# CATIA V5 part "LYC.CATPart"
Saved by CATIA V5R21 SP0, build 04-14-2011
Part number: LYC.SLDPRT
Bounding box of the stored display mesh (mm): x -1.7 to 1.7, y -1.65 to 1.65, z -1.105 to 0.8
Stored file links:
  C:\Users\user\Desktop\CATIA文件\0-最新文件\LYC\LYC.CATPart
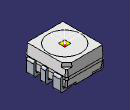
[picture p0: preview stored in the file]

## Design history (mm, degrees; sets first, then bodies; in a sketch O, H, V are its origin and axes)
AxisSystem1: origin (-0.0017, 0.0021, 0.8), X (-1, 0, 0), Y (0, -1, 0), Z (0, 0, 1)
Set1
  DatumSurface1 to DatumSurface139
  Circle1: stored without definition
  Circle2: stored without definition
  DatumCurve1 to DatumCurve5
  Line1 to Line5: stored without definition
  DatumCurve6 to DatumCurve12
  Line6: stored without definition
  Circle3 to Circle8: stored without definition
  Line7: stored without definition
  Circle9: stored without definition
  Line8: stored without definition
  Circle10: stored without definition
  Line9: stored without definition
  Circle11: stored without definition
  Line10: stored without definition
  Circle12: stored without definition
  Line11 to Line13: stored without definition
  Circle13: stored without definition
  Line14: stored without definition
  Circle14: stored without definition
  Line15 to Line23: stored without definition
  Circle15: stored without definition
  Line24: stored without definition
  Circle16: stored without definition
  Line25 to Line27: stored without definition
  Circle17: stored without definition
  Line28: stored without definition
  Circle18: stored without definition
  Line29 to Line40: stored without definition
  Circle19: stored without definition
  Line41: stored without definition
  Circle20: stored without definition
  Line42 to Line44: stored without definition
  Circle21: stored without definition
  Line45: stored without definition
  Circle22: stored without definition
  Line46 to Line54: stored without definition
  Circle23: stored without definition
  Line55: stored without definition
  Circle24: stored without definition
  Line56 to Line58: stored without definition
  Circle25: stored without definition
  Line59: stored without definition
  Circle26: stored without definition
  Line60 to Line65: stored without definition
  Circle27 to Circle29: stored without definition
  Line66: stored without definition
  Circle30: stored without definition
  Line67: stored without definition
  Circle31: stored without definition
  Line68: stored without definition
  Circle32: stored without definition
  Line69: stored without definition
  Circle33 to Circle38: stored without definition
  Line70: stored without definition
  Line71: stored without definition
  Circle39: stored without definition
  Circle40: stored without definition
  Line72 to Line78: stored without definition
  DatumCurve13
  DatumCurve14
  Line79: stored without definition
  Line80: stored without definition
  Circle41: stored without definition
  Line81: stored without definition
  DatumCurve15
  Line82: stored without definition
  Line83: stored without definition
  DatumCurve16
  Line84: stored without definition
  Circle42: stored without definition
  Line85: stored without definition
  DatumCurve17
  Line86: stored without definition
  DatumCurve18
  Line87 to Line89: stored without definition
  DatumCurve19
  DatumCurve20
  Line90: stored without definition
  Circle43: stored without definition
  Line91: stored without definition
  Circle44: stored without definition
  Circle45: stored without definition
  Line92: stored without definition
  Circle46 to Circle49: stored without definition
  Line93: stored without definition
  Circle50: stored without definition
  Line94 to Line99: stored without definition
  DatumCurve21
  Line100: stored without definition
  Circle51: stored without definition
  Line101: stored without definition
  Line102: stored without definition
  DatumCurve22
  Line103 to Line111: stored without definition
  DatumCurve23
  Line112: stored without definition
  DatumCurve24
  Line113: stored without definition
  Circle52: stored without definition
  DatumCurve25
  Line114 to Line116: stored without definition
  Circle53: stored without definition
  Line117 to Line124: stored without definition
  DatumCurve26
  Line125: stored without definition
  DatumCurve27 to DatumCurve29
  Circle54: stored without definition
  Line126: stored without definition
  Circle55: stored without definition
  Line127 to Line129: stored without definition
  DatumCurve30
  Line130: stored without definition
  Line131: stored without definition
  DatumCurve31
  Line132 to Line139: stored without definition
  DatumCurve32
  Line140 to Line143: stored without definition
  DatumCurve33
  Line144 to Line169: stored without definition
  Circle56: stored without definition
  Line170: stored without definition
  Circle57: stored without definition
  Line171 to Line173: stored without definition
  Circle58: stored without definition
  Line174: stored without definition
  Circle59: stored without definition
  Line175 to Line183: stored without definition
  Circle60: stored without definition
  Line184: stored without definition
  Circle61: stored without definition
  Line185 to Line187: stored without definition
  Circle62: stored without definition
  Circle63: stored without definition
  Line188: stored without definition
  Circle64: stored without definition
  Circle65: stored without definition
  Line189 to Line191: stored without definition
  Circle66: stored without definition
  Line192: stored without definition
  Circle67: stored without definition
  Line193 to Line201: stored without definition
  Circle68: stored without definition
  Line202: stored without definition
  Circle69: stored without definition
  Line203 to Line205: stored without definition
  Circle70: stored without definition
  Line206: stored without definition
  Circle71: stored without definition
  Line207: stored without definition
  Line208: stored without definition
  Circle72: stored without definition
  Line209: stored without definition
  Circle73: stored without definition
  Line210 to Line212: stored without definition
  Circle74: stored without definition
  Line213: stored without definition
  Circle75: stored without definition
  Line214 to Line216: stored without definition
  Circle76: stored without definition
  Line217 to Line219: stored without definition
  Circle77: stored without definition
  Line220 to Line227: stored without definition
  Circle78: stored without definition
  Line228: stored without definition
  Line229: stored without definition
  Circle79: stored without definition
  Line230: stored without definition
  Circle80: stored without definition
  Line231: stored without definition
  Circle81: stored without definition
  Line232 to Line234: stored without definition
  Circle82: stored without definition
  Line235: stored without definition
  Circle83: stored without definition
  Line236: stored without definition
  Circle84: stored without definition
  Line237 to Line239: stored without definition
  Circle85: stored without definition
  Line240 to Line245: stored without definition
  Circle86: stored without definition
  Line246 to Line248: stored without definition
  Circle87: stored without definition
  Line249: stored without definition
  Line250: stored without definition
  Circle88: stored without definition
  Line251 to Line258: stored without definition
  Point1 "几何中心&发光中心（测试原点）": type Center, Curve edge of DatumSurface70
  Point2 "虚拟坐标": (0.0114, 0.0108, -0.134), relative to Point1, in AxisSystem1
Body1 (main body)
